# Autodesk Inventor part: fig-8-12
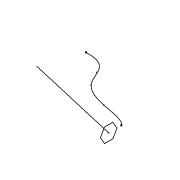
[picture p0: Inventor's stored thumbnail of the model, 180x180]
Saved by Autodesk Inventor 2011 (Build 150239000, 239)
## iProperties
Created: 2004-05
Part Number: fig-8-12
Document SubType Name: Modeling
Designer: CADCIM Technologies
Manufacturer: Standard
Standards Organization: Custom
Density: 1 g/cm^3
Author: CADCIM Technologies
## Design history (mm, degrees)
workplane "Work Plane2"
sketch "Sketch7"
  geometry: L1 (-42.583, 6.068)-(-42.583, 0.37) reference; 5 further points
  constraints: 1 point on line, 5 other
sketch "Sketch8"
  geometry: L1 (-42.583, 3.219)-(-107.269, 18.236); L2 (-42.583, 6.068)-(-42.583, 0.37) reference
  constraints: 2 end point, 1 midpoint
sketch "Sketch2"
  geometry: L1 (-5.697, 0)-(-2.849, 4.934); L2 (-2.849, 4.934)-(2.849, 4.934); L3 (2.849, 4.934)-(5.697, 0); L4 (5.697, 0)-(2.849, -4.934); L5 (2.849, -4.934)-(-2.849, -4.934); L6 (-2.849, -4.934)-(-5.697, 0); 2 further points
  constraints: 12 end point, 1 coincident, 12 other
